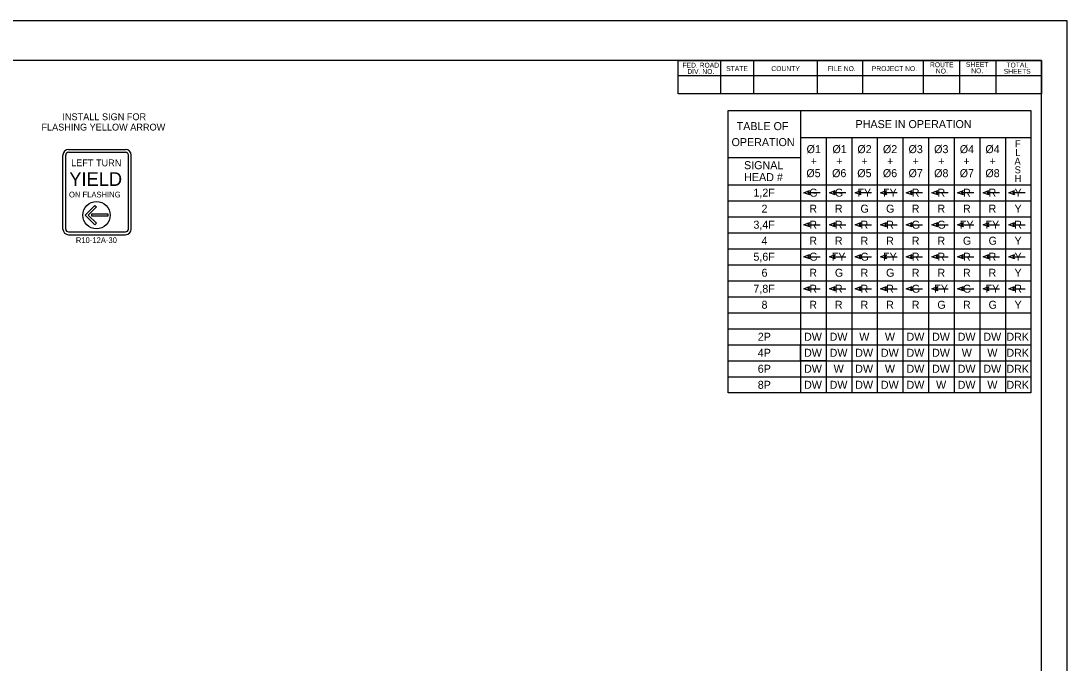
# Model space of a CAD drawing. Extents: x 0 to 3.01, y -0.05 to 1.83.
# Drawn here: x 1.467 to 3, y 0.892 to 1.833 of the extents above; entities that cross this region are included whole.
import ezdxf

# ---------------------------------------------------------------- set-up
doc = ezdxf.new("R2010")
doc.units = 0
for name, color, linetype in [('Default', 7, 'Continuous'), ('RD_SHT_IplotShp', 7, 'Continuous'), ('TR_TS_Border', 7, 'Continuous'), ('TR_TS_PD_Signs', 7, 'Continuous'), ('TR_TS_Phase1', 7, 'Continuous'), ('TR_TS_Phase1-5', 7, 'Continuous'), ('TR_TS_Phase2', 7, 'Continuous'), ('TR_TS_Phase3', 7, 'Continuous'), ('TR_TS_Phase4', 7, 'Continuous'), ('TR_TS_Phase5', 7, 'Continuous'), ('TR_TS_Phase6', 7, 'Continuous'), ('TR_TS_Phase7', 7, 'Continuous'), ('TR_TS_Phase8', 7, 'Continuous'), ('TR_TS_Text', 7, 'Continuous')]:
    doc.layers.add(name, color=color, linetype=linetype)

msp = doc.modelspace()

# ---------------------------------------------------------------- linework, layer by layer
at = {"layer": 'Default'}
for p, q in [((2.6094, 1.702), (2.6094, 1.2885)), ((2.6094, 1.6623), (2.9471, 1.6623)), ((2.6469, 1.6623), (2.6469, 1.2885)), ((2.6844, 1.6623), (2.6844, 1.2885)), ((2.7219, 1.6623), (2.7219, 1.2885)), ((2.7595, 1.6623), (2.7595, 1.2885)), ((2.797, 1.6623), (2.797, 1.2885)), ((2.8345, 1.6623), (2.8345, 1.2885)), ((2.8721, 1.6623), (2.8721, 1.2885)), ((2.9096, 1.6623), (2.9096, 1.2885)), ((2.5035, 1.633), (2.6094, 1.633)), ((2.5035, 1.5934), (2.9471, 1.5934)), ((2.5035, 1.5699), (2.9471, 1.5699)), ((2.5035, 1.5465), (2.9471, 1.5465)), ((2.5035, 1.523), (2.9471, 1.523)), ((2.5035, 1.4996), (2.9471, 1.4996)), ((2.5035, 1.4761), (2.9471, 1.4761)), ((2.5035, 1.4527), (2.9471, 1.4527)), ((2.5035, 1.4292), (2.9471, 1.4292)), ((2.5035, 1.4058), (2.9471, 1.4058)), ((2.5035, 1.3823), (2.9471, 1.3823)), ((2.5035, 1.3588), (2.9471, 1.3588)), ((2.5035, 1.3354), (2.9471, 1.3354)), ((2.5035, 1.3119), (2.9471, 1.3119))]:
    msp.add_line(p, q, dxfattribs=at)
for points in [[(2.5035, 1.702), (2.9471, 1.702), (2.9471, 1.2885), (2.5035, 1.2885)], [(2.6094, 1.3588), (2.6469, 1.3588), (2.6469, 1.3354), (2.6094, 1.3354)]]:
    msp.add_lwpolyline(points, close=True, dxfattribs=at)
at = {"layer": 'RD_SHT_IplotShp'}
msp.add_lwpolyline([(0, 0), (3, 0), (3, 1.8333), (0, 1.8333)], close=True, dxfattribs=at)
at = {"layer": 'TR_TS_Border'}
for p, q in [((2.9419, 1.8333), (0.031, 1.8333)), ((3, 0), (3, 1.8333)), ((2.9623, 1.7754), (0.1686, 1.7754)), ((2.4925, 1.7266), (2.4925, 1.7754)), ((2.5412, 1.7266), (2.5412, 1.7754)), ((2.6343, 1.7266), (2.6343, 1.7754)), ((2.7008, 1.7266), (2.7008, 1.7754)), ((2.7895, 1.7266), (2.7895, 1.7754)), ((2.8427, 1.7266), (2.8427, 1.7754)), ((2.8959, 1.7266), (2.8959, 1.7754)), ((2.9623, 0.0475), (2.9623, 1.7754)), ((2.4304, 1.7532), (2.9623, 1.7532))]:
    msp.add_line(p, q, dxfattribs=at)
msp.add_lwpolyline([(2.9623, 1.7754), (2.9623, 1.7266), (2.4304, 1.7266), (2.4304, 1.7754)], close=True, dxfattribs=at)
at = {"layer": 'TR_TS_PD_Signs'}
for p, q in [((1.537, 1.6451), (1.6204, 1.6451)), ((1.537, 1.641), (1.6204, 1.641)), ((1.5287, 1.5284), (1.5287, 1.6368)), ((1.5328, 1.5284), (1.5328, 1.6368)), ((1.6246, 1.5284), (1.6246, 1.6368)), ((1.6288, 1.5284), (1.6288, 1.6368)), ((1.5612, 1.5488), (1.5755, 1.5631)), ((1.5755, 1.5345), (1.5612, 1.5488)), ((1.5779, 1.5608), (1.5659, 1.5488)), ((1.5659, 1.5488), (1.5779, 1.5368)), ((1.5755, 1.5631), (1.5779, 1.5608)), ((1.5779, 1.5368), (1.5755, 1.5345)), ((1.537, 1.5242), (1.6204, 1.5242)), ((1.537, 1.52), (1.6204, 1.52))]:
    msp.add_line(p, q, dxfattribs=at)
msp.add_lwpolyline([(1.5712, 1.5505), (1.5946, 1.5505), (1.5946, 1.5471), (1.5712, 1.5471), (1.5712, 1.5505)], dxfattribs=at)
msp.add_circle((1.5779, 1.5488), 0.02, dxfattribs=at)
for centre, radius, start, end in [((1.537, 1.6368), 0.00834, 90, 180), ((1.537, 1.6368), 0.00417, 90, 180), ((1.6204, 1.6368), 0.00834, 360, 90), ((1.6204, 1.6368), 0.00417, 360, 90), ((1.537, 1.5284), 0.00834, 180, 270), ((1.537, 1.5284), 0.00417, 180, 270), ((1.6204, 1.5284), 0.00417, 270, 360), ((1.6204, 1.5284), 0.00834, 270, 360)]:
    msp.add_arc(centre, radius, start, end, dxfattribs=at)
at = {"layer": 'TR_TS_Phase1'}
for p, q in [((2.6203, 1.5817), (2.6383, 1.5817)), ((2.6579, 1.5817), (2.6758, 1.5817)), ((2.6954, 1.5817), (2.7133, 1.5817)), ((2.7329, 1.5817), (2.7509, 1.5817)), ((2.7704, 1.5817), (2.7884, 1.5817)), ((2.808, 1.5817), (2.8259, 1.5817)), ((2.8455, 1.5817), (2.8635, 1.5817)), ((2.883, 1.5817), (2.901, 1.5817)), ((2.9206, 1.5817), (2.9385, 1.5817))]:
    msp.add_line(p, q, dxfattribs=at)
for points in [[(2.6229, 1.5786), (2.6142, 1.5816), (2.6228, 1.5848), (2.6203, 1.5817)], [(2.6604, 1.5786), (2.6518, 1.5816), (2.6603, 1.5848), (2.6579, 1.5817)], [(2.6979, 1.5786), (2.6893, 1.5816), (2.6978, 1.5848), (2.6954, 1.5817)], [(2.7354, 1.5786), (2.7268, 1.5816), (2.7354, 1.5848), (2.7329, 1.5817)], [(2.773, 1.5786), (2.7644, 1.5816), (2.7729, 1.5848), (2.7704, 1.5817)], [(2.8105, 1.5786), (2.8019, 1.5816), (2.8104, 1.5848), (2.808, 1.5817)], [(2.848, 1.5786), (2.8394, 1.5816), (2.848, 1.5848), (2.8455, 1.5817)], [(2.8856, 1.5786), (2.8769, 1.5816), (2.8855, 1.5848), (2.883, 1.5817)], [(2.9231, 1.5786), (2.9145, 1.5816), (2.923, 1.5848), (2.9206, 1.5817)]]:
    msp.add_lwpolyline(points, close=True, dxfattribs=at)
at = {"layer": 'TR_TS_Phase3'}
for p, q in [((2.6203, 1.5348), (2.6383, 1.5348)), ((2.6579, 1.5348), (2.6758, 1.5348)), ((2.6954, 1.5348), (2.7133, 1.5348)), ((2.7329, 1.5348), (2.7509, 1.5348)), ((2.7704, 1.5348), (2.7884, 1.5348)), ((2.808, 1.5348), (2.8259, 1.5348)), ((2.8455, 1.5348), (2.8635, 1.5348)), ((2.883, 1.5348), (2.901, 1.5348)), ((2.9206, 1.5348), (2.9385, 1.5348))]:
    msp.add_line(p, q, dxfattribs=at)
for points in [[(2.6229, 1.5317), (2.6142, 1.5347), (2.6228, 1.5379), (2.6203, 1.5348)], [(2.6604, 1.5317), (2.6518, 1.5347), (2.6603, 1.5379), (2.6579, 1.5348)], [(2.6979, 1.5317), (2.6893, 1.5347), (2.6978, 1.5379), (2.6954, 1.5348)], [(2.7354, 1.5317), (2.7268, 1.5347), (2.7354, 1.5379), (2.7329, 1.5348)], [(2.773, 1.5317), (2.7644, 1.5347), (2.7729, 1.5379), (2.7704, 1.5348)], [(2.8105, 1.5317), (2.8019, 1.5347), (2.8104, 1.5379), (2.808, 1.5348)], [(2.848, 1.5317), (2.8394, 1.5347), (2.848, 1.5379), (2.8455, 1.5348)], [(2.8856, 1.5317), (2.8769, 1.5347), (2.8855, 1.5379), (2.883, 1.5348)], [(2.9231, 1.5317), (2.9145, 1.5347), (2.923, 1.5379), (2.9206, 1.5348)]]:
    msp.add_lwpolyline(points, close=True, dxfattribs=at)
at = {"layer": 'TR_TS_Phase5'}
for p, q in [((2.6203, 1.4879), (2.6383, 1.4879)), ((2.6579, 1.4879), (2.6758, 1.4879)), ((2.6954, 1.4879), (2.7133, 1.4879)), ((2.7329, 1.4879), (2.7509, 1.4879)), ((2.7704, 1.4879), (2.7884, 1.4879)), ((2.808, 1.4879), (2.8259, 1.4879)), ((2.8455, 1.4879), (2.8635, 1.4879)), ((2.883, 1.4879), (2.901, 1.4879)), ((2.9206, 1.4879), (2.9385, 1.4879))]:
    msp.add_line(p, q, dxfattribs=at)
for points in [[(2.6229, 1.4848), (2.6142, 1.4877), (2.6228, 1.491), (2.6203, 1.4879)], [(2.6604, 1.4848), (2.6518, 1.4877), (2.6603, 1.491), (2.6579, 1.4879)], [(2.6979, 1.4848), (2.6893, 1.4877), (2.6978, 1.491), (2.6954, 1.4879)], [(2.7354, 1.4848), (2.7268, 1.4877), (2.7354, 1.491), (2.7329, 1.4879)], [(2.773, 1.4848), (2.7644, 1.4877), (2.7729, 1.491), (2.7704, 1.4879)], [(2.8105, 1.4848), (2.8019, 1.4877), (2.8104, 1.491), (2.808, 1.4879)], [(2.848, 1.4848), (2.8394, 1.4877), (2.848, 1.491), (2.8455, 1.4879)], [(2.8856, 1.4848), (2.8769, 1.4877), (2.8855, 1.491), (2.883, 1.4879)], [(2.9231, 1.4848), (2.9145, 1.4877), (2.923, 1.491), (2.9206, 1.4879)]]:
    msp.add_lwpolyline(points, close=True, dxfattribs=at)
at = {"layer": 'TR_TS_Phase7'}
for p, q in [((2.6203, 1.4409), (2.6383, 1.4409)), ((2.6579, 1.4409), (2.6758, 1.4409)), ((2.6954, 1.4409), (2.7133, 1.4409)), ((2.7329, 1.4409), (2.7509, 1.4409)), ((2.7704, 1.4409), (2.7884, 1.4409)), ((2.808, 1.4409), (2.8259, 1.4409)), ((2.8455, 1.4409), (2.8635, 1.4409)), ((2.883, 1.4409), (2.901, 1.4409)), ((2.9206, 1.4409), (2.9385, 1.4409))]:
    msp.add_line(p, q, dxfattribs=at)
for points in [[(2.6229, 1.4379), (2.6142, 1.4408), (2.6228, 1.4441), (2.6203, 1.4409)], [(2.6604, 1.4379), (2.6518, 1.4408), (2.6603, 1.4441), (2.6579, 1.4409)], [(2.6979, 1.4379), (2.6893, 1.4408), (2.6978, 1.4441), (2.6954, 1.4409)], [(2.7354, 1.4379), (2.7268, 1.4408), (2.7354, 1.4441), (2.7329, 1.4409)], [(2.773, 1.4379), (2.7644, 1.4408), (2.7729, 1.4441), (2.7704, 1.4409)], [(2.8105, 1.4379), (2.8019, 1.4408), (2.8104, 1.4441), (2.808, 1.4409)], [(2.848, 1.4379), (2.8394, 1.4408), (2.848, 1.4441), (2.8455, 1.4409)], [(2.8856, 1.4379), (2.8769, 1.4408), (2.8855, 1.4441), (2.883, 1.4409)], [(2.9231, 1.4379), (2.9145, 1.4408), (2.923, 1.4441), (2.9206, 1.4409)]]:
    msp.add_lwpolyline(points, close=True, dxfattribs=at)

# ---------------------------------------------------------------- texts
at = {"layer": 'Default'}
for s, height, p in [('PHASE IN OPERATION', 0.011728, (2.6901, 1.6763)), ('TABLE OF ', 0.01173, (2.5159, 1.6733)), ('OPERATION', 0.01173, (2.5084, 1.6499)), ('F', 0.0102, (2.9237, 1.6482)), ('L', 0.0102, (2.9241, 1.6355)), ('SIGNAL ', 0.01173, (2.5267, 1.6161)), ('A', 0.0102, (2.9229, 1.6228)), ('HEAD #', 0.01173, (2.5269, 1.5986)), ('S', 0.0102, (2.9233, 1.6101)), ('H', 0.0102, (2.9231, 1.5974)), ('2P', 0.01173, (2.5468, 1.3647)), ('DW', 0.01173, (2.6146, 1.3647)), ('DW', 0.01173, (2.6521, 1.3647)), ('W', 0.0117, (2.6955, 1.3647)), ('W', 0.0117, (2.7331, 1.3647)), ('DW', 0.01173, (2.7647, 1.3647)), ('DW', 0.01173, (2.8022, 1.3647)), ('DW', 0.01173, (2.8397, 1.3647)), ('DW', 0.01173, (2.8773, 1.3647)), ('DRK', 0.01173, (2.9111, 1.3647)), ('4P', 0.01173, (2.5468, 1.3412)), ('DW', 0.01173, (2.6146, 1.3412)), ('DW', 0.01173, (2.6521, 1.3412)), ('DW', 0.01173, (2.6896, 1.3412)), ('DW', 0.01173, (2.7272, 1.3412)), ('DW', 0.01173, (2.7647, 1.3412)), ('DW', 0.01173, (2.8022, 1.3412)), ('W', 0.0117, (2.8457, 1.3412)), ('W', 0.0117, (2.8832, 1.3412)), ('DRK', 0.01173, (2.9111, 1.3412)), ('6P', 0.01173, (2.5468, 1.3178)), ('DW', 0.01173, (2.6146, 1.3178)), ('W', 0.0117, (2.658, 1.3178)), ('DW', 0.01173, (2.6896, 1.3178)), ('W', 0.0117, (2.7331, 1.3178)), ('DW', 0.01173, (2.7647, 1.3178)), ('DW', 0.01173, (2.8022, 1.3178)), ('DW', 0.01173, (2.8397, 1.3178)), ('DW', 0.01173, (2.8773, 1.3178)), ('DRK', 0.01173, (2.9111, 1.3178)), ('8P', 0.01173, (2.5468, 1.2943)), ('DW', 0.01173, (2.6146, 1.2943)), ('DW', 0.01173, (2.6521, 1.2943)), ('DW', 0.01173, (2.6896, 1.2943)), ('DW', 0.01173, (2.7272, 1.2943)), ('DW', 0.01173, (2.7647, 1.2943)), ('W', 0.0117, (2.8081, 1.2943)), ('DW', 0.01173, (2.8397, 1.2943)), ('W', 0.0117, (2.8832, 1.2943)), ('DRK', 0.01173, (2.9111, 1.2943))]:
    msp.add_text(s, height=height, dxfattribs=at).set_placement(p)
at = {"layer": 'TR_TS_Border'}
for s, height, p in [('FED. ROAD', 0.00715, (2.4364, 1.7649)), ('DIV. NO.', 0.00715, (2.4436, 1.7557)), ('STATE', 0.00715, (2.5005, 1.7599)), ('COUNTY', 0.00715, (2.5667, 1.7599)), ('FILE NO.', 0.00715, (2.6492, 1.7599)), ('PROJECT NO.', 0.007148, (2.7139, 1.7599)), ('ROUTE', 0.00715, (2.7991, 1.7655)), ('NO.', 0.00715, (2.8077, 1.7563)), ('SHEET', 0.00715, (2.8518, 1.766)), ('NO.', 0.00715, (2.8596, 1.7567)), ('SHEETS', 0.00715, (2.9072, 1.7559)), ('TOTAL', 0.00715, (2.9111, 1.7651))]:
    msp.add_text(s, height=height, dxfattribs=at).set_placement(p)
at = {"layer": 'TR_TS_PD_Signs'}
for s, height, p in [('LEFT TURN', 0.01001, (1.5407, 1.6204)), ('YIELD', 0.02002, (1.538, 1.5916)), ('ON FLASHING', 0.00834, (1.5376, 1.5747))]:
    msp.add_text(s, height=height, rotation=360, dxfattribs=at).set_placement(p)
at = {"layer": 'TR_TS_Phase1'}
for s, height, p in [('Ø1', 0.01173, (2.6183, 1.6396)), ('Ø1', 0.01173, (2.6562, 1.6396)), ('1,2F', 0.01173, (2.5404, 1.5758)), ('G', 0.0117, (2.6223, 1.5758)), ('G', 0.0117, (2.6598, 1.5758)), ('FY', 0.01173, (2.6928, 1.5758)), ('FY', 0.01173, (2.7303, 1.5758)), ('R', 0.0117, (2.7724, 1.5758)), ('R', 0.0117, (2.81, 1.5758)), ('R', 0.0117, (2.8475, 1.5758)), ('R', 0.0117, (2.885, 1.5758)), ('Y', 0.0117, (2.923, 1.5758))]:
    msp.add_text(s, height=height, dxfattribs=at).set_placement(p)
at = {"layer": 'TR_TS_Phase1-5'}
for p in [(2.6243, 1.622), (2.6618, 1.622), (2.6987, 1.622), (2.7362, 1.622), (2.7737, 1.622), (2.8112, 1.622), (2.8481, 1.622), (2.8865, 1.622)]:
    msp.add_text('+', height=0.0117, rotation=360, dxfattribs=at).set_placement(p)
at = {"layer": 'TR_TS_Phase2'}
for s, height, p in [('Ø2', 0.01173, (2.6927, 1.6396)), ('Ø2', 0.01173, (2.7302, 1.6396)), ('2', 0.0117, (2.5523, 1.5524)), ('R', 0.0117, (2.6223, 1.5524)), ('R', 0.0117, (2.6598, 1.5524)), ('G', 0.0117, (2.6973, 1.5524)), ('G', 0.0117, (2.7348, 1.5524)), ('R', 0.0117, (2.7724, 1.5524)), ('R', 0.0117, (2.81, 1.5524)), ('R', 0.0117, (2.8475, 1.5524)), ('R', 0.0117, (2.885, 1.5524)), ('Y', 0.0117, (2.923, 1.5524))]:
    msp.add_text(s, height=height, dxfattribs=at).set_placement(p)
at = {"layer": 'TR_TS_Phase3'}
for s, height, p in [('Ø3', 0.01173, (2.7677, 1.6396)), ('Ø3', 0.01173, (2.8052, 1.6396)), ('3,4F', 0.01173, (2.5404, 1.5289)), ('R', 0.0117, (2.6223, 1.5289)), ('R', 0.0117, (2.6598, 1.5289)), ('R', 0.0117, (2.6974, 1.5289)), ('R', 0.0117, (2.7349, 1.5289)), ('G', 0.0117, (2.7724, 1.5289)), ('G', 0.0117, (2.8099, 1.5289)), ('FY', 0.01173, (2.8429, 1.5289)), ('FY', 0.01173, (2.8804, 1.5289)), ('R', 0.0117, (2.9226, 1.5289))]:
    msp.add_text(s, height=height, dxfattribs=at).set_placement(p)
at = {"layer": 'TR_TS_Phase4'}
for s, height, p in [('Ø4', 0.01173, (2.8428, 1.6396)), ('Ø4', 0.01173, (2.8803, 1.6396)), ('4', 0.0117, (2.5523, 1.5054)), ('R', 0.0117, (2.6223, 1.5054)), ('R', 0.0117, (2.6598, 1.5054)), ('R', 0.0117, (2.6974, 1.5054)), ('R', 0.0117, (2.7349, 1.5054)), ('R', 0.0117, (2.7724, 1.5054)), ('R', 0.0117, (2.81, 1.5054)), ('G', 0.0117, (2.8474, 1.5054)), ('G', 0.0117, (2.885, 1.5054)), ('Y', 0.0117, (2.923, 1.5054))]:
    msp.add_text(s, height=height, dxfattribs=at).set_placement(p)
at = {"layer": 'TR_TS_Phase5'}
for s, height, p in [('Ø5', 0.01173, (2.618, 1.6044)), ('Ø5', 0.01173, (2.6926, 1.6044)), ('5,6F', 0.01173, (2.5404, 1.482)), ('G', 0.0117, (2.6223, 1.482)), ('FY', 0.01173, (2.6552, 1.482)), ('G', 0.0117, (2.6973, 1.482)), ('FY', 0.01173, (2.7303, 1.482)), ('R', 0.0117, (2.7724, 1.482)), ('R', 0.0117, (2.81, 1.482)), ('R', 0.0117, (2.8475, 1.482)), ('R', 0.0117, (2.885, 1.482)), ('Y', 0.0117, (2.923, 1.482))]:
    msp.add_text(s, height=height, dxfattribs=at).set_placement(p)
at = {"layer": 'TR_TS_Phase6'}
for s, height, p in [('Ø6', 0.01173, (2.6557, 1.6044)), ('Ø6', 0.01173, (2.7301, 1.6044)), ('6', 0.0117, (2.5523, 1.4585)), ('R', 0.0117, (2.6223, 1.4585)), ('G', 0.0117, (2.6598, 1.4585)), ('R', 0.0117, (2.6974, 1.4585)), ('G', 0.0117, (2.7348, 1.4585)), ('R', 0.0117, (2.7724, 1.4585)), ('R', 0.0117, (2.81, 1.4585)), ('R', 0.0117, (2.8475, 1.4585)), ('R', 0.0117, (2.885, 1.4585)), ('Y', 0.0117, (2.923, 1.4585))]:
    msp.add_text(s, height=height, dxfattribs=at).set_placement(p)
at = {"layer": 'TR_TS_Phase7'}
for s, height, p in [('Ø7', 0.01173, (2.7677, 1.6044)), ('Ø7', 0.01173, (2.8427, 1.6044)), ('7,8F', 0.01173, (2.5404, 1.4351)), ('R', 0.0117, (2.6223, 1.4351)), ('R', 0.0117, (2.6598, 1.4351)), ('R', 0.0117, (2.6974, 1.4351)), ('R', 0.0117, (2.7349, 1.4351)), ('G', 0.0117, (2.7724, 1.4351)), ('FY', 0.01173, (2.8054, 1.4351)), ('G', 0.0117, (2.8474, 1.4351)), ('FY', 0.01173, (2.8804, 1.4351)), ('R', 0.0117, (2.9226, 1.4351))]:
    msp.add_text(s, height=height, dxfattribs=at).set_placement(p)
at = {"layer": 'TR_TS_Phase8'}
for s, height, p in [('Ø8', 0.01173, (2.8052, 1.6044)), ('Ø8', 0.01173, (2.8803, 1.6044)), ('8', 0.0117, (2.5523, 1.4116)), ('R', 0.0117, (2.6223, 1.4116)), ('R', 0.0117, (2.6598, 1.4116)), ('R', 0.0117, (2.6974, 1.4116)), ('R', 0.0117, (2.7349, 1.4116)), ('R', 0.0117, (2.7724, 1.4116)), ('G', 0.0117, (2.8099, 1.4116)), ('R', 0.0117, (2.8475, 1.4116)), ('G', 0.0117, (2.885, 1.4116)), ('Y', 0.0117, (2.923, 1.4116))]:
    msp.add_text(s, height=height, dxfattribs=at).set_placement(p)
at = {"layer": 'TR_TS_Text'}
for s, height, p in [('INSTALL SIGN FOR ', 0.010008, (1.5279, 1.6879)), ('FLASHING YELLOW ARROW', 0.010008, (1.4972, 1.6727)), ('R10-12A-30', 0.00834, (1.5476, 1.5079))]:
    msp.add_text(s, height=height, rotation=360, dxfattribs=at).set_placement(p)

doc.saveas('drawing.dxf')
